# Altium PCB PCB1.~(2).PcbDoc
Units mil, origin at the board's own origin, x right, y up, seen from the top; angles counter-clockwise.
Board outline 6000 x 4000 mil, 2 copper layers (Top Layer, Bottom Layer); 82 components, 57 nets, 195 pads, 0 vias.
Unrouted connection lines stored in the file: 130.
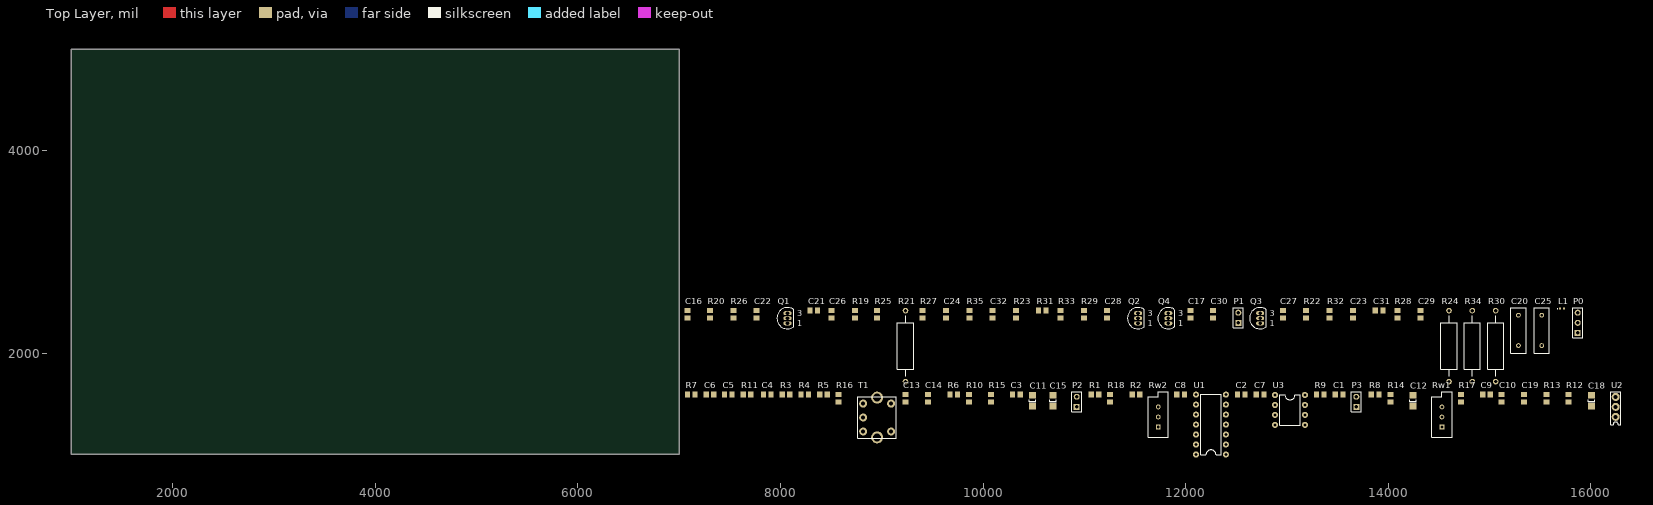
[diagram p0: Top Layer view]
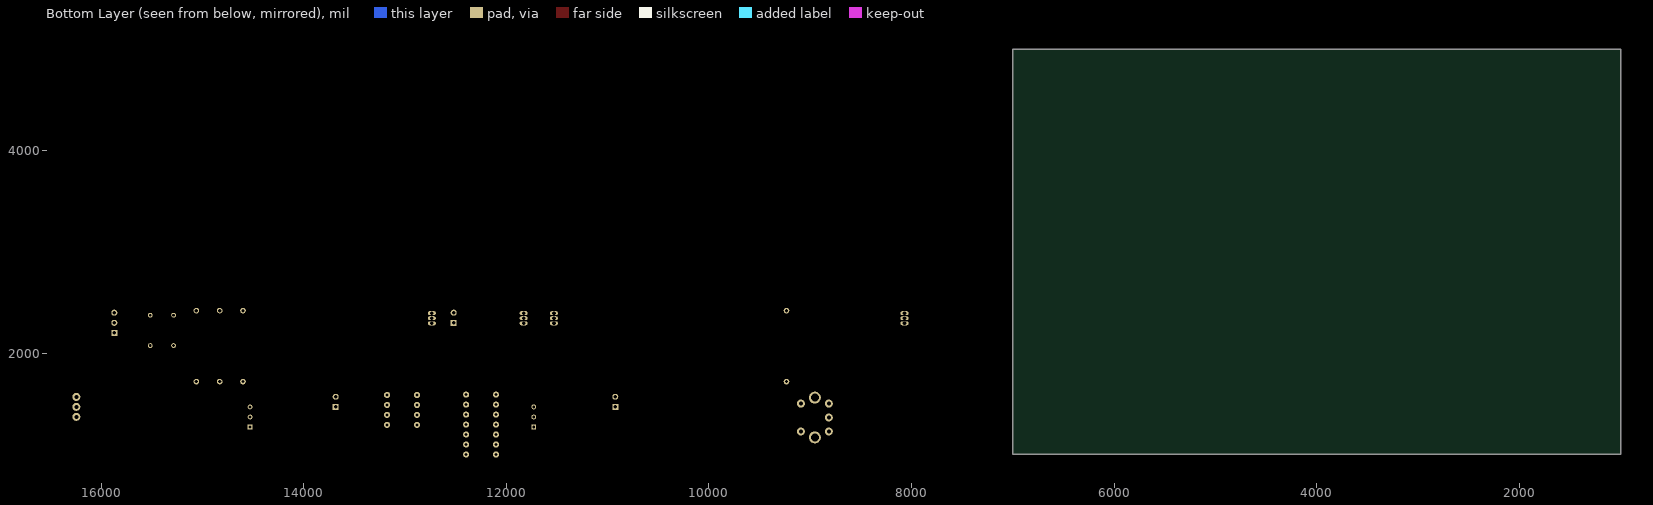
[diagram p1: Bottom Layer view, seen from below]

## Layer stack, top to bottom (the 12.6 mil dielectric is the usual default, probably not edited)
Top Layer: signal copper 1.4
Dielectric: dielectric 12.6, FR-4, Dk 4.8
Bottom Layer: signal copper 1.4

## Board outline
1000,1000 7000,1000 7000,5000 1000,5000

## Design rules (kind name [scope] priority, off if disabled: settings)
Clearance [All] p1: gap=10
PolygonConnect [All] p1: connectstyle=Relief reliefconductorwidth=10 reliefentries=4 polygonreliefangle="90 Angle"
RoomDefinition Sheet2 [InComponentClass('Sheet2')] p1: confinementstyle=ConfineIn formatcopy=TRUE lockcomponents=FALSE outline 7045,1680 15945,1680 15945,2560 7045,2560
RoomDefinition Sheet1 [InComponentClass('Sheet1')] p2: confinementstyle=ConfineIn formatcopy=TRUE lockcomponents=FALSE outline 7045,960 16315,960 16315,2560 7045,2560
RoutingVias [All] p1: holewidth=28 width=50 viastyle="Through Hole" minholewidth=28 minwidth=50 maxholewidth=28 maxwidth=50
SilkscreenOverComponentPads [All] p1: minsilkscreentomaskgap=10
SolderMaskExpansion [All] p1: expansion=4
TestPointUsage [All] p1: valid=0 allowmultiple=FALSE
Testpoint [All] p1: side=15 testpointundercomponent=TRUE minsize=40 maxsize=100 preferedsize=60 minholesize=0 maxholesize=40 preferedholesize=32 testpointgrid=1 style=1023 order=0123456789
Width [All] p1: maxlimit=100 minlimit=10 preferedwidth=10 minimp=50.000000 maximp=50.000000 favimp=50.000000
23 further rules are at their usual default settings.

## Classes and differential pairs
component class Sheet2: C16 C17 C20 C21 C22 C23 C24 C25 C26 C27 C28 C29 C30 C31 C32 L1 P0 P1 Q1 Q2 Q3 Q4 R19 R20 R21 R22 R23 R24 R25 R26 R27 R28 R29 R30 R31 R32 R33 R34 R35 T2 T3 T4 T5
component class Sheet1: C1 C2 C3 C4 C5 C6 C7 C8 C9 C10 C11 C12 C13 C14 C15 C18 C19 P2 P3 R1 R2 R3 R4 R5 R6 R7 R8 R9 R10 R11 R12 R13 R14 R15 R16 R17 R18 Rw1 Rw2 T1 U1 U2 U3

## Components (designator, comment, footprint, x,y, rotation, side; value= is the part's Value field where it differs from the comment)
C1 "Cap" 2012[0805] 13515,1590 r0 top
C2 "Cap" 2012[0805] 12550,1590 r0 top
C3 "Cap" 2012[0805] 10330,1590 r0 top
C4 "Cap" 2012[0805] 7870,1590 r0 top
C5 "Cap" 2012[0805] 7485,1590 r0 top
C6 "Cap" 2012[0805] 7305,1590 r0 top
C7 "Cap" 2012[0805] 12735,1590 r0 top
C8 "Cap" 2012[0805] 11950,1590 r0 top
C9 "Cap" 2012[0805] 14970,1590 r0 top
C10 "Cap" 2012[0805] 15120,1555 r90 top
C11 "Cap Pol1" C1206 10490,1530 r90 top
C12 "Cap Pol1" C1206 14245,1530 r90 top
C13 "Cap" 2012[0805] 9235,1555 r90 top
C14 "Cap" 2012[0805] 9455,1555 r90 top
C15 "Cap Pol1" C1206 10690,1530 r90 top
C16 "Cap" 2012[0805] 7085,2385 r90 top
C17 "Cap" 2012[0805] 12050,2385 r90 top
C18 "Cap Pol1" C1206 16005,1530 r90 top
C19 "Cap" 2012[0805] 15340,1555 r90 top
C20 "Cap" RAD-0.3 15285,2225 r90 top
C21 "Cap" 2012[0805] 8330,2420 r0 top
C22 "Cap" 2012[0805] 7765,2385 r90 top
C23 "Cap" 2012[0805] 13650,2385 r90 top
C24 "Cap" 2012[0805] 9635,2385 r90 top
C25 "Cap" RAD-0.3 15515,2225 r90 top
C26 "Cap" 2012[0805] 8505,2385 r90 top
C27 "Cap" 2012[0805] 12960,2385 r90 top
C28 "Cap" 2012[0805] 11225,2385 r90 top
C29 "Cap" 2012[0805] 14320,2385 r90 top
C30 "Cap" 2012[0805] 12270,2385 r90 top
C31 "Cap" 2012[0805] 13910,2420 r0 top
C32 "Cap" 2012[0805] 10095,2385 r90 top
L1 "Inductor" 0402-A 15715,2440 r0 top
P0 "Header 3" HDR1X3 15870,2200 r90 top
P1 "Header 2" HDR1X2 12520,2300 r90 top
P2 "Header 2" HDR1X2 10925,1470 r90 top
P3 "Header 2" HDR1X2 13685,1470 r90 top
Q1 "NPN" TO-226 8070,2345 r0 top
Q2 "NPN" TO-226 11530,2345 r0 top
Q3 "NPN" TO-226 12735,2345 r0 top
Q4 "NPN" TO-226 11830,2345 r0 top
R1 "Res1" 2012[0805] 11105,1590 r0 top
R2 "Res1" 2012[0805] 11510,1590 r0 top
R3 "Res1" 2012[0805] 8055,1590 r0 top
R4 "Res1" 2012[0805] 8240,1590 r0 top
R5 "Res1" 2012[0805] 8425,1590 r0 top
R6 "Res1" 2012[0805] 9710,1590 r0 top
R7 "Res1" 2012[0805] 7120,1590 r0 top
R8 "Res1" 2012[0805] 13870,1590 r0 top
R9 "Res1" 2012[0805] 13330,1590 r0 top
R10 "Res1" 2012[0805] 9860,1555 r90 top
R11 "Res1" 2012[0805] 7670,1590 r0 top
R12 "Res1" 2012[0805] 15780,1555 r90 top
R13 "Res1" 2012[0805] 15560,1555 r90 top
R14 "Res1" 2012[0805] 14020,1555 r90 top
R15 "Res1" 2012[0805] 10080,1555 r90 top
R16 "Res1" 2012[0805] 8575,1555 r90 top
R17 "Res1" 2012[0805] 14720,1555 r90 top
R18 "Res1" 2012[0805] 11255,1555 r90 top
R19 "Res1" 2012[0805] 8735,2385 r90 top
R20 "Res1" 2012[0805] 7305,2385 r90 top
R21 "Res Adj1" AXIAL-0.7 9235,2070 r90 top
R22 "Res1" 2012[0805] 13190,2385 r90 top
R23 "Res1" 2012[0805] 10325,2385 r90 top
R24 "Res Adj1" AXIAL-0.7 14600,2070 r90 top
R25 "Res1" 2012[0805] 8955,2385 r90 top
R26 "Res1" 2012[0805] 7535,2385 r90 top
R27 "Res1" 2012[0805] 9405,2385 r90 top
R28 "Res1" 2012[0805] 14090,2385 r90 top
R29 "Res1" 2012[0805] 10995,2385 r90 top
R30 "Res Adj1" AXIAL-0.7 15060,2070 r90 top
R31 "Res1" 2012[0805] 10585,2420 r0 top
R32 "Res1" 2012[0805] 13420,2385 r90 top
R33 "Res1" 2012[0805] 10765,2385 r90 top
R34 "Res Adj1" AXIAL-0.7 14830,2070 r90 top
R35 "Res1" 2012[0805] 9865,2385 r90 top
Rw1 "RPot" VR5 14530,1370 r90 top
Rw2 "RPot" VR5 11730,1370 r90 top
T1 "zhongzhou" zhongzhou 8955,1365 r0 top
U1 "MC1496" MC1496 12250,1295 r90 top
U2 "LM7808" LM7808 16245,1470 r90 top
U3 "LM741" LM741 13030,1440 r0 top

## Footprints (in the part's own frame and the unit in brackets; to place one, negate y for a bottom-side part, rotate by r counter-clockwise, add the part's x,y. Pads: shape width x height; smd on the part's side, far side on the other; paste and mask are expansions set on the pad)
0402-A [mm] "Chip Inductor; Body 1 x 0.5 mm (LxW typ)"
  rect 0.6x0.5 smd: 1(-0.5,0) 2(0.5,0)
  silkscreen extent -1.1,-0.15 -1.1,0.15
2012[0805] [mm] "Chip Resistor; Body 2.0 x 1.3 mm (LxW typ)"
  rect 1.3x1.5 smd: 1(-0.95,0) 2(0.95,0)
AXIAL-0.7 [mm] "Variable Resistor; 2 Leads"
  round 1.4 hole 0.85: 1(-8.89,0) 2(8.89,0)
  silkscreen extent -7.62,-2.03 7.62,2.03
C1206 [mm] "Chip Capacitor; Body 3.2 x 1.6 mm (LxW typ)"
  rect 1.6x1.8 smd: 1(-1.4,0) 2(1.4,0)
  silkscreen extent -0.3,-0.8 0.3,0.8
HDR1X2 [mm] "Connector; Header; 2 Position"
  rect 1.5x1.5 hole 0.9: 1(0,0)
  round 1.5 hole 0.9: 2(2.54,0)
  silkscreen extent -1.27,-1.27 3.81,1.27
HDR1X3 [mm] "Connector; Header; 3 Position"
  rect 1.5x1.5 hole 0.9: 1(0,0)
  round 1.5 hole 0.9: 2(2.54,0) 3(5.08,0)
  silkscreen extent -1.27,-1.27 6.35,1.27
LM741 [mil]
  round 60 hole 30: 1(-147.64,147.64) 2(-147.64,49.21) 3(-147.64,-49.21) 4(-147.64,-147.64) 5(147.64,-147.64) 6(147.64,-49.21) 7(147.64,49.21) 8(147.64,147.64)
  silkscreen extent -100,-150 100,150
LM7808 [mm]
  round 2 hole 1: 1(-2.5,0) 2(0,0) 3(2.5,0)
  silkscreen extent -4.44,-1.27 3.81,1.27
MC1496 [mil]
  round 60 hole 30: 1(-295.28,-147.64) 2(-196.85,-147.64) 3(-98.43,-147.64) 4(0,-147.64) 5(98.43,-147.64) 6(196.85,-147.64) 7(295.28,-147.64) 8(295.28,147.64) 9(196.85,147.64) 10(98.43,147.64) 11(0,147.64) 12(-98.43,147.64) 13(-196.85,147.64) 14(-295.28,147.64)
  silkscreen extent -300,-100 300,100
RAD-0.3 [mm] "Capacitor; 2 Leads"
  round 1.2 hole 0.7: 1(-3.81,0) 2(3.81,0)
  silkscreen extent -5.71,-1.91 5.71,1.91
TO-226 [mm] "TO, Flat Index; 3 In-Line, Axial Leads; Body Dia. 4.8mm; Leads 0.55 x 0.51 mm (max)"
  oval 2x1 hole 0.9: 1(0,-1.27) 2(0,0) 3(0,1.27)
  silkscreen extent -2.65,-2.65 1.55,2.65
VR5 [mm] "Potentiometer; 3 Leads"
  rect 1.2x1.2 hole 0.7: 1(-2.54,0)
  round 1.2 hole 0.7: 2(0,0) 3(2.54,0)
  silkscreen extent -5.08,-2.54 6.35,2.54
zhongzhou [mm]
  round 2 hole 1: 1(-3.5,3.5) 2(-3.5,0) 3(-3.5,-3.5) 4(3.5,-3.5) 5(3.5,3.5)
  round 3 hole 2: 6(0,5) 7(0,-5)
  silkscreen extent -4.83,-5.21 4.83,5.21

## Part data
C1 C2 C3 C4 C5 C6 C7 C8 C9 C10 C13 C14 C16 C17 C19 C20 C21 C22 C23 C24 C25 C26 C27 C28 C29 C30 C31 C32: "Capacitor"
C11 C12 C15 C18: "Polarized Capacitor (Radial)"
P0: "Header, 3-Pin"
P1 P2 P3: "Header, 2-Pin"
Q1 Q2 Q3 Q4: "NPN Bipolar Transistor"
R1 R2 R3 R4 R5 R6 R7 R8 R9 R10 R11 R12 R13 R14 R15 R16 R17 R18 R19 R20 R22 R23 R25 R26 R27 R28 R29 R31 R32 R33 R35: "Resistor"
R21 R24 R30 R34: "Variable Resistor"
Rw1 Rw2: "Potentiometer"

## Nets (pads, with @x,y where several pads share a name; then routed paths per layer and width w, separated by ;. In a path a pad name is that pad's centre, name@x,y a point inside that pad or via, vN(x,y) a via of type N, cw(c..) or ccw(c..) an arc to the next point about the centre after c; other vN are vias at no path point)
+12V: C18.1 C23.1 C25.2 C29.1 C31.1 L1.2 R12.1 R21.1 R24.1 R25.2 R30.1 R34.1
-8V: C7.2 C13.2 P0.2 Rw2.3 U1.14 U3.4
GND: C4.1 C5.1 C6.1 C7.1 C8.1 C13.1 C14.1 C16.2 C18.2 C19.1 C20.1 C22.2 C24.1 C25.1 C32.1 P0.1 P1.1 P2.2 R3.1 R4.1 R7.1 R11.1 R16.1 R20.1 R23.1 R26.1 R27.1 R29.1 R31.1 R33.1 R35.1 T1.3 T1.4 T1.6 T1.7 U2.2
NetC1_1: C1.1 P3.2
NetC1_2: C1.2 C2.2 R9.1
NetC2_1: C2.1 C4.2 R10.1 T1.1
NetC3_1: C3.1 R10.2
NetC3_2: C3.2 R1.1 R3.2 U1.1
NetC5_2: C5.2 R2.1 R4.2 U1.4
NetC6_2: C6.2 C11.1 R6.1 U1.6
NetC8_2: C8.2 C12.1 R8.1 U1.12
NetC9_1: C9.1 Rw1.1 U1.8
NetC9_2: C9.2 C10.1 R12.2 R13.1 Rw1.3
NetC10_2: C10.2 R13.2
NetC11_2: C11.2 R15.1
NetC12_2: C12.2 R14.1
NetC14_2: C14.2 C15.1 R18.1
NetC15_2: C15.2 P2.1
NetC16_1: C16.1 Q1.2 R19.1 R20.2
NetC17_1: C17.1 P1.2
NetC17_2: C17.2 Q2.2 R22.1 R23.2
NetC19_2: C19.2 U2.3 U3.7
NetC20_2: C20.2 L1.1 P0.3
NetC21_1: C21.1 C26.2 Q1.1 R25.1
NetC21_2: C21.2 C22.1
NetC23_2: C23.2
NetC24_2: C24.2 Q2.3 R27.2
NetC26_1: C26.1
NetC27_1: C27.1
NetC27_2: C27.2 Q3.2 R28.1 R29.2
NetC28_1: C28.1 Q3.3 R31.2
NetC28_2: C28.2
NetC29_2: C29.2
NetC30_1: C30.1
NetC30_2: C30.2 Q4.2 R32.1 R33.2
NetC31_2: C31.2
NetC32_2: C32.2 Q4.3 R35.2
NetQ1_3: Q1.3 R26.2
NetQ2_1: Q2.1
NetQ3_1: Q3.1
NetQ4_1: Q4.1
NetR1_2: R1.2 Rw2.2
NetR2_2: R2.2 Rw2.1
NetR5_1: R5.1 U1.3
NetR5_2: R5.2 U1.2
NetR6_2: R6.2 R8.2 U2.1
NetR7_2: R7.2 U1.5
NetR9_2: R9.2 Rw1.2 U1.10
NetR11_2: R11.2 T1.5
NetR14_2: R14.2 R17.1 U3.2
NetR15_2: R15.2 R16.2 U3.3
NetR17_2: R17.2 R18.2 U3.6
NetR19_2: R19.2 R21.2
NetR22_2: R22.2 R24.2
NetR28_2: R28.2 R30.2
NetR32_2: R32.2 R34.2
ZHONGFANG: P3.1
pads on no net: T1.2 U1.7 U1.9 U1.11 U1.13 U3.1 U3.5 U3.8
